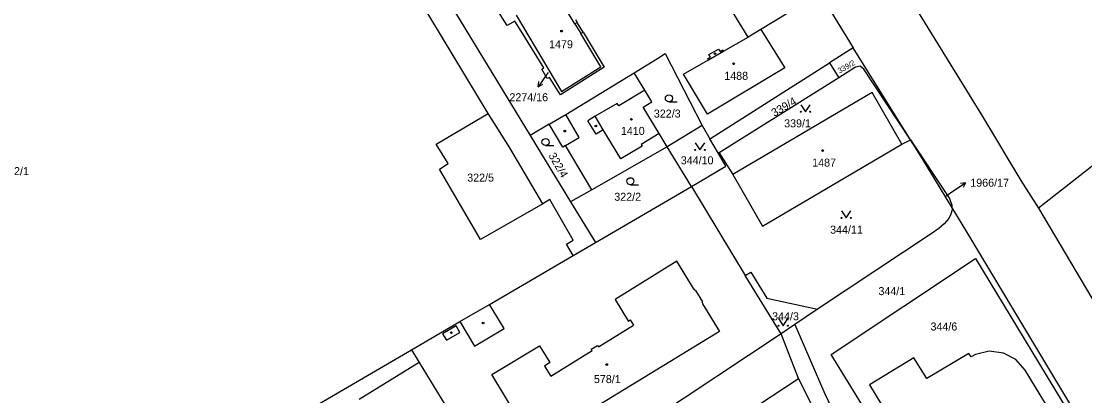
# Model space of a CAD drawing. Extents: x -679220 to -673243, y -1075091 to -1066557.
# Drawn here: x -675968.3 to -675742.5, y -1072555.7 to -1072476.3 of the extents above; entities that cross this region are included whole.
import ezdxf

# ---------------------------------------------------------------- set-up
doc = ezdxf.new("R2010")
doc.units = 0
for name, color, linetype in [('Hranice parcel', 7, 'Continuous'), ('Parcelní čísla', 7, 'Continuous'), ('Pop  PČ popisy', 7, 'Continuous'), ('Vnitřní kresba', 7, 'Continuous'), ('Značky budov', 7, 'Continuous'), ('Značky kultur', 7, 'Continuous')]:
    doc.layers.add(name, color=color, linetype=linetype)

msp = doc.modelspace()

# ---------------------------------------------------------------- linework, layer by layer
at = {"layer": 'Hranice parcel'}
for p, q in [((-675915.69, -1072409.65), (-675860.23, -1072500.52)), ((-675869.15, -1072495.9), (-675916.48, -1072417.57)), ((-675813.96, -1072479.68), (-675823.65, -1072463.72)), ((-675850.64, -1072475.95), (-675850.24, -1072476.57)), ((-675849, -1072478.61), (-675850.24, -1072476.57)), ((-675849, -1072478.61), (-675844.5, -1072486.02)), ((-675811.24, -1072478.03), (-675813.96, -1072479.68)), ((-675791.64, -1072481.95), (-675796.64, -1072485.13)), ((-675779.44, -1072501.5), (-675791.64, -1072481.95)), ((-675796.64, -1072485.13), (-675794.68, -1072488.32)), ((-675794.68, -1072488.32), (-675820.08, -1072504.23)), ((-675856.2, -1072498.13), (-675860.23, -1072500.52)), ((-675823.72, -1072498.41), (-675831.13, -1072502.94)), ((-675823.72, -1072498.41), (-675822.06, -1072501.26)), ((-675860.23, -1072500.52), (-675851.64, -1072514.61)), ((-675820.26, -1072504.34), (-675822.06, -1072501.26)), ((-675781.33, -1072502.4), (-675779.44, -1072501.5)), ((-675831.13, -1072502.94), (-675847.17, -1072512.07)), ((-675825.98, -1072511.4), (-675831.13, -1072502.94)), ((-675820.26, -1072504.34), (-675820.08, -1072504.23)), ((-675820.08, -1072504.23), (-675817.21, -1072508.85)), ((-675847.17, -1072512.07), (-675851.64, -1072514.61)), ((-675846.36, -1072523.26), (-675825.98, -1072511.4)), ((-675825.98, -1072511.4), (-675814.59, -1072530.25)), ((-675851.64, -1072514.61), (-675846.36, -1072523.26)), ((-675851.07, -1072526), (-675846.36, -1072523.26)), ((-675806.92, -1072542.65), (-675814.59, -1072530.25)), ((-675799.2, -1072537.4), (-675804, -1072540.66)), ((-675804, -1072540.66), (-675806.92, -1072542.65)), ((-675806.92, -1072542.65), (-675864.4, -1072580.56)), ((-675803.25, -1072552.13), (-675806.92, -1072542.65)), ((-675912.55, -1072561.77), (-675885.46, -1072546.01)), ((-675814.67, -1072559.62), (-675803.25, -1072552.13))]:
    msp.add_line(p, q, dxfattribs=at)
for points in [[(-675789.23, -1072455.87), (-675764.41, -1072496.19), (-675756.04, -1072510.12), (-675752.3, -1072515.97)], [(-675815.23, -1072458.61), (-675812.3, -1072463.43), (-675811.92, -1072463.2), (-675811.51, -1072463.88), (-675810.97, -1072463.55), (-675809.75, -1072465.56), (-675810.29, -1072465.89), (-675809.87, -1072466.58), (-675810.25, -1072466.81), (-675805.54, -1072474.57), (-675811.24, -1072478.03)], [(-675844.5, -1072486.02), (-675853.83, -1072491.94), (-675856.1, -1072488.21), (-675856.6, -1072488.49), (-675857.75, -1072486.5), (-675857.35, -1072486.18), (-675862.12, -1072478.41), (-675863.52, -1072476.32), (-675865.1, -1072477.2), (-675867.43, -1072473.56), (-675875.26, -1072460.62)], [(-675802.38, -1072465.38), (-675798.17, -1072471.25), (-675791.64, -1072481.95)], [(-675850.24, -1072476.57), (-675850.75, -1072476.88), (-675855.01, -1072469.85)], [(-675863.19, -1072475.02), (-675853.58, -1072491.19), (-675845.23, -1072485.98), (-675849.51, -1072478.92), (-675849, -1072478.61)], [(-675811.24, -1072478.03), (-675806.14, -1072486.17), (-675822.55, -1072496.04), (-675827.65, -1072487.56), (-675822.36, -1072484.51), (-675822.51, -1072484.24), (-675821.97, -1072483.93), (-675822.28, -1072483.39), (-675820.22, -1072482.21), (-675819.91, -1072482.74), (-675819.31, -1072482.4), (-675819.16, -1072482.67), (-675813.96, -1072479.68)], [(-675838.16, -1072487.22), (-675833.21, -1072484.2), (-675831.54, -1072483.13), (-675823.72, -1072498.41)], [(-675708.65, -1072482.25), (-675713.36, -1072485.87), (-675728.81, -1072497.64), (-675752.3, -1072515.97)], [(-675822.06, -1072501.26), (-675821.96, -1072501.2), (-675796.64, -1072485.13)], [(-675856.2, -1072498.13), (-675852.64, -1072496.06), (-675838.16, -1072487.22)], [(-675831.13, -1072502.94), (-675832.84, -1072500.11), (-675836.22, -1072494.55), (-675834.39, -1072493.44), (-675835.9, -1072490.95), (-675838.16, -1072487.22)], [(-675779.44, -1072501.5), (-675789.4, -1072486.46), (-675790.15, -1072485.86), (-675791.15, -1072486.06), (-675794.68, -1072488.32)], [(-675781.33, -1072502.4), (-675787.59, -1072491.44), (-675817.21, -1072508.85)], [(-675857.57, -1072515.01), (-675870.78, -1072522.63), (-675879.52, -1072507.66), (-675877.65, -1072506.52), (-675880.19, -1072502.4), (-675869.15, -1072495.9)], [(-675857.57, -1072515.01), (-675864.58, -1072503.15), (-675869.15, -1072495.9)], [(-675847.17, -1072512.07), (-675852.75, -1072502.68), (-675853.32, -1072503.02), (-675856.2, -1072498.13)], [(-675770.65, -1072515.77), (-675776.68, -1072505.85), (-675778.36, -1072503.24), (-675779.44, -1072501.5)], [(-675779.44, -1072501.5), (-675771.21, -1072513.91), (-675770.68, -1072515.32), (-675770.65, -1072515.77)], [(-675817.21, -1072508.85), (-675810.88, -1072519.75), (-675781.33, -1072502.4)], [(-675825.98, -1072511.4), (-675818.66, -1072507.08), (-675820.26, -1072504.34)], [(-675851.07, -1072526), (-675852.5, -1072523.58), (-675851.11, -1072522.78), (-675856.03, -1072514.12), (-675857.57, -1072515.01)], [(-675770.65, -1072515.77), (-675770.62, -1072516.31), (-675770.91, -1072517.26), (-675771.33, -1072518.18), (-675772.29, -1072519.29), (-675773.45, -1072520.28), (-675775.1, -1072521.43), (-675799.2, -1072537.4)], [(-675740.73, -1072565.51), (-675767.49, -1072520.97), (-675770.65, -1072515.77)], [(-675752.3, -1072515.97), (-675736.4, -1072542.72), (-675736.11, -1072543.3)], [(-675885.46, -1072546.01), (-675875.16, -1072540.02), (-675868.89, -1072536.38), (-675851.07, -1072526)], [(-675787.38, -1072561.47), (-675796.29, -1072547), (-675765.67, -1072526.64), (-675741.69, -1072566.13)], [(-675814.59, -1072530.25), (-675813.4, -1072529.51), (-675809.94, -1072535.07), (-675799.2, -1072537.4)], [(-675804, -1072540.66), (-675797.68, -1072555.37), (-675793.38, -1072564.25), (-675788.79, -1072572.83), (-675782.79, -1072582.7), (-675778.12, -1072589.82)], [(-675885.46, -1072546.01), (-675883.81, -1072548.72), (-675878.39, -1072557.61), (-675864.4, -1072580.56)], [(-675765.07, -1072579.51), (-675747.5, -1072568.78), (-675748.6, -1072566.77), (-675748.24, -1072566.53), (-675747.35, -1072565.49), (-675747.06, -1072564.07), (-675747.52, -1072562.8), (-675755.12, -1072550.33), (-675757.07, -1072548.08), (-675759.72, -1072546.69), (-675762.77, -1072546.27), (-675765.68, -1072547.04), (-675766.55, -1072547.48), (-675767.1, -1072546.79), (-675775.96, -1072552.09), (-675778.73, -1072547.69), (-675788.15, -1072553.46), (-675784.36, -1072559.7)], [(-675785.29, -1072584.89), (-675792.61, -1072572.7), (-675794.85, -1072568.73), (-675803.25, -1072552.13)]]:
    msp.add_lwpolyline(points, dxfattribs=at)
at = {"layer": 'Pop  PČ popisy'}
for p, q in [((-675856.82, -1072487.76), (-675858.54, -1072490.22)), ((-675856.44, -1072487.21), (-675856.82, -1072487.76)), ((-675858.54, -1072490.22), (-675858.38, -1072489.11)), ((-675858.54, -1072490.22), (-675857.56, -1072489.69)), ((-675770.24, -1072512.25), (-675767.75, -1072510.57)), ((-675767.75, -1072510.57), (-675768.86, -1072510.72)), ((-675767.75, -1072510.57), (-675768.3, -1072511.55)), ((-675771.91, -1072513.38), (-675770.24, -1072512.25))]:
    msp.add_line(p, q, dxfattribs=at)
at = {"layer": 'Vnitřní kresba'}
for p, q in [((-675850.75, -1072476.88), (-675849.51, -1072478.92)), ((-675822.36, -1072484.51), (-675819.16, -1072482.67)), ((-675835.9, -1072490.95), (-675841.43, -1072494.25)), ((-675841.75, -1072493.75), (-675846.45, -1072496.47)), ((-675841.43, -1072494.25), (-675841.75, -1072493.75)), ((-675849.83, -1072500.96), (-675852.64, -1072496.06)), ((-675846.45, -1072496.47), (-675847.98, -1072497.41)), ((-675844.7, -1072499.34), (-675846.45, -1072496.47)), ((-675846.23, -1072500.28), (-675847.98, -1072497.41)), ((-675844.7, -1072499.34), (-675846.23, -1072500.28)), ((-675840.95, -1072505.47), (-675844.7, -1072499.34)), ((-675852.75, -1072502.68), (-675849.83, -1072500.96)), ((-675832.84, -1072500.11), (-675836.67, -1072502.43)), ((-675836.43, -1072502.81), (-675840.95, -1072505.47)), ((-675836.67, -1072502.43), (-675836.43, -1072502.81)), ((-675829.1, -1072527.24), (-675842.18, -1072535.37)), ((-675825.44, -1072533.24), (-675829.1, -1072527.24)), ((-675825.35, -1072533.19), (-675825.44, -1072533.24)), ((-675825.17, -1072533.49), (-675825.35, -1072533.19)), ((-675842.18, -1072535.37), (-675839.37, -1072539.99)), ((-675825.05, -1072533.41), (-675825.17, -1072533.49)), ((-675823.59, -1072535.8), (-675825.05, -1072533.41)), ((-675865.79, -1072541.49), (-675868.89, -1072536.38)), ((-675823.72, -1072535.88), (-675823.59, -1072535.8)), ((-675823.54, -1072536.18), (-675823.72, -1072535.88)), ((-675823.63, -1072536.24), (-675823.54, -1072536.18)), ((-675823.63, -1072536.24), (-675820.02, -1072542.14)), ((-675875.16, -1072540.02), (-675872.04, -1072545.22)), ((-675839.37, -1072539.99), (-675838.97, -1072539.66)), ((-675838.97, -1072539.66), (-675838.28, -1072540.8)), ((-675875.98, -1072540.95), (-675878.83, -1072542.59)), ((-675875.19, -1072542.33), (-675875.98, -1072540.95)), ((-675872.04, -1072545.22), (-675865.79, -1072541.49)), ((-675820.02, -1072542.14), (-675859.34, -1072566.06)), ((-675845.75, -1072545.38), (-675838.28, -1072540.8)), ((-675878.83, -1072542.59), (-675878.04, -1072543.97)), ((-675878.04, -1072543.97), (-675875.19, -1072542.33)), ((-675868.39, -1072551.27), (-675858.25, -1072545.14)), ((-675858.25, -1072545.14), (-675856.04, -1072548.67)), ((-675855.86, -1072551.59), (-675847.07, -1072546.19)), ((-675847.25, -1072545.89), (-675845.93, -1072545.09)), ((-675847.07, -1072546.19), (-675847.25, -1072545.89)), ((-675845.93, -1072545.09), (-675845.75, -1072545.38)), ((-675883.81, -1072548.72), (-675896.57, -1072556.57)), ((-675856.04, -1072548.67), (-675857.18, -1072549.45)), ((-675859.34, -1072566.06), (-675868.39, -1072551.27)), ((-675857.18, -1072549.45), (-675855.86, -1072551.59))]:
    msp.add_line(p, q, dxfattribs=at)
at = {"layer": 'Značky budov'}
for centre in [(-675853.57, -1072478.41), (-675820.97, -1072483.19), (-675817.01, -1072485.33), (-675838.75, -1072497.13), (-675846.28, -1072498.53), (-675852.88, -1072499.62), (-675798.11, -1072503.74), (-675876.97, -1072542.39), (-675870.23, -1072540.34), (-675843.97, -1072549.13)]:
    msp.add_circle(centre, 0.175, dxfattribs=at)
at = {"layer": 'Značky kultur'}
for p, q in [((-675830.77, -1072493.41), (-675829.02, -1072493.41)), ((-675856.98, -1072502.69), (-675855.23, -1072502.69)), ((-675838.95, -1072511), (-675837.2, -1072511))]:
    msp.add_line(p, q, dxfattribs=at)
for points in [[(-675802.76, -1072494.01), (-675801.76, -1072495.51), (-675800.76, -1072494.01)], [(-675825.17, -1072502.11), (-675824.17, -1072503.61), (-675823.17, -1072502.11)], [(-675794.13, -1072516.52), (-675793.13, -1072518.02), (-675792.13, -1072516.52)], [(-675807.51, -1072539.4), (-675806.51, -1072540.9), (-675805.51, -1072539.4)]]:
    msp.add_lwpolyline(points, dxfattribs=at)
for centre, radius in [((-675830.77, -1072492.66), 0.75), ((-675802.76, -1072495.51), 0.1), ((-675800.76, -1072495.51), 0.1), ((-675856.98, -1072501.94), 0.75), ((-675825.17, -1072503.61), 0.1), ((-675823.17, -1072503.61), 0.1), ((-675838.95, -1072510.25), 0.75), ((-675794.13, -1072518.02), 0.1), ((-675792.13, -1072518.02), 0.1), ((-675807.51, -1072540.9), 0.1), ((-675805.51, -1072540.9), 0.1)]:
    msp.add_circle(centre, radius, dxfattribs=at)

# ---------------------------------------------------------------- texts
at = {"layer": 'Parcelní čísla'}
for s, p in [('1479', (-675856.21, -1072482.04)), ('1488', (-675819.01, -1072488.74)), ('2274/16', (-675864.65, -1072493.28)), ('322/3', (-675833.97, -1072496.75)), ('339/1', (-675806.29, -1072498.82)), ('1410', (-675840.97, -1072500.43)), ('344/10', (-675828.25, -1072506.66)), ('1487', (-675800.34, -1072507.14)), ('322/1', (-675972.39, -1072508.95)), ('322/5', (-675873.61, -1072510.33)), ('1966/17', (-675766.76, -1072511.41)), ('322/2', (-675842.37, -1072514.39)), ('344/11', (-675796.53, -1072521.37)), ('344/1', (-675786.27, -1072534.41)), ('344/3', (-675808.85, -1072539.75)), ('344/6', (-675775.21, -1072541.92)), ('578/1', (-675846.7, -1072553.07))]:
    msp.add_text(s, height=1.7, dxfattribs=at).set_placement(p)
for s, height, rotation, p in [('339/2', 1.14, 30, (-675794.51, -1072487.42)), ('339/4', 1.7, 30, (-675808.4, -1072496.63)), ('322/4', 1.7, 300, (-675856.41, -1072504.78))]:
    msp.add_text(s, height=height, rotation=rotation, dxfattribs=at).set_placement(p)

doc.saveas('drawing.dxf')
